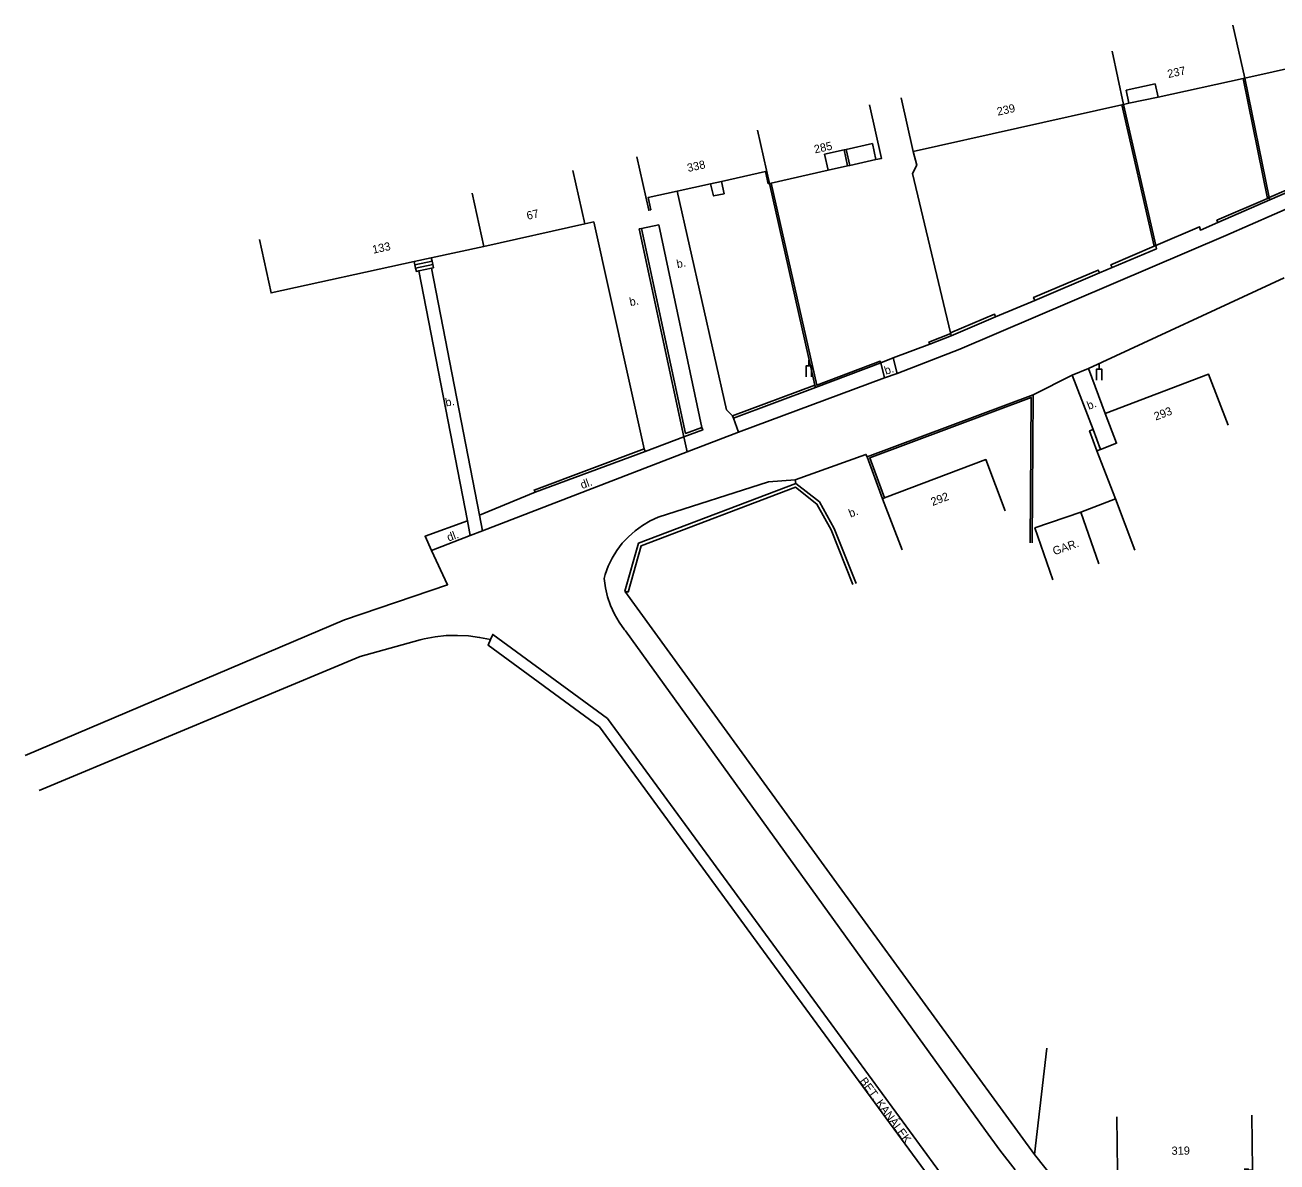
# Model space of a CAD drawing. Extents: x -582162 to -561283, y -1187583 to -1183539.
# Drawn here: x -575255.7 to -575141.2, y -1183913 to -1183809.1 of the extents above; entities that cross this region are included whole.
import ezdxf

# ---------------------------------------------------------------- set-up
doc = ezdxf.new("R2010")
doc.units = 0
for name, color, linetype in [('Vrstva 1', 7, 'Continuous'), ('Vrstva 10', 7, 'Continuous'), ('Vrstva 14', 7, 'Continuous'), ('Vrstva 4', 7, 'Continuous'), ('Vrstva 6', 7, 'Continuous'), ('Vrstva 9', 7, 'Continuous')]:
    doc.layers.add(name, color=color, linetype=linetype)

# ---------------------------------------------------------------- blocks, each defined once
blk = doc.blocks.new('4.120')
at = {"layer": 'Vrstva 1'}
blk.add_line((0, 2), (0, 3), dxfattribs=at)
blk.add_lwpolyline([(-0.5, 0), (-0.5, 2), (0.5, 2), (0.5, 0)], dxfattribs=at)

msp = doc.modelspace()

# ---------------------------------------------------------------- linework, layer by layer
at = {"layer": 'Vrstva 10'}
for points in [[(-575191.01, -1183844.78), (-575191.57, -1183844.23), (-575196.06, -1183824.24)], [(-575175.95, -1183840.92), (-575170.24, -1183838.68), (-575145.92, -1183828.3), (-575137, -1183824.39)], [(-575204.52, -1183827.23), (-575203.7, -1183827.05), (-575199.08, -1183847.81)], [(-575193.82, -1183845.85), (-575197.76, -1183827.33), (-575199.33, -1183827.64)], [(-575218.53, -1183831.28), (-575214.16, -1183853.85)], [(-575215.26, -1183854.39), (-575219.68, -1183831.52)], [(-575140.57, -1183832.16), (-575158.46, -1183840.46)], [(-575158.46, -1183840.46), (-575159.96, -1183841.06)], [(-575156.93, -1183844.57), (-575158.46, -1183840.46)], [(-575190.48, -1183846.26), (-575177.11, -1183841.3)], [(-575177.11, -1183841.3), (-575175.95, -1183840.92)], [(-575159.96, -1183841.06), (-575163.54, -1183842.86)], [(-575159.96, -1183841.06), (-575158.04, -1183846.03)], [(-575190.93, -1183844.99), (-575190.48, -1183846.26)], [(-575199, -1183848.03), (-575195.47, -1183846.69)], [(-575195.47, -1183846.69), (-575195.17, -1183848.06)], [(-575195.17, -1183848.06), (-575190.48, -1183846.26)], [(-575213.88, -1183855.28), (-575195.17, -1183848.06)], [(-575178.7, -1183848.54), (-575178.81, -1183848.31), (-575185.28, -1183850.64)], [(-575185.28, -1183850.64), (-575187.72, -1183850.81), (-575197.8, -1183854.03), (-575198.55, -1183854.38), (-575199.25, -1183854.8), (-575199.92, -1183855.28), (-575200.53, -1183855.83), (-575201.09, -1183856.43), (-575201.58, -1183857.09), (-575202.01, -1183857.79), (-575202.37, -1183858.53), (-575202.66, -1183859.3), (-575202.76, -1183859.65), (-575202.64, -1183860.49), (-575202.43, -1183861.32), (-575202.16, -1183862.13), (-575201.8, -1183862.9), (-575201.38, -1183863.64), (-575200.89, -1183864.34), (-575200.8, -1183864.45), (-575183.27, -1183888.75), (-575167.87, -1183910.11), (-575166.56, -1183911.93), (-575165.18, -1183913.7)], [(-575185.22, -1183850.97), (-575185.28, -1183850.64)], [(-575214.16, -1183853.85), (-575209.06, -1183851.77)], [(-575214.16, -1183853.85), (-575213.88, -1183855.28)], [(-575215.26, -1183854.39), (-575219.13, -1183855.79), (-575218.53, -1183857.08)], [(-575215.01, -1183855.72), (-575215.26, -1183854.39)], [(-575215.01, -1183855.72), (-575213.88, -1183855.28)], [(-575218.53, -1183857.08), (-575215.01, -1183855.72)], [(-575255.7, -1183875.83), (-575226.48, -1183863.42), (-575217.07, -1183860.22), (-575218.53, -1183857.08)], [(-575254.42, -1183879.04), (-575225.06, -1183866.77), (-575219.58, -1183865.26), (-575219.21, -1183865.17), (-575218.2, -1183864.98), (-575217.19, -1183864.87), (-575216.17, -1183864.85), (-575215.15, -1183864.9), (-575214.14, -1183865.03), (-575213.14, -1183865.24)], [(-575213.14, -1183865.24), (-575213.37, -1183865.75), (-575203.18, -1183873.21), (-575188.19, -1183893.71), (-575166.83, -1183922.84)], [(-575213.14, -1183865.24), (-575212.94, -1183864.77), (-575202.43, -1183872.46), (-575187.34, -1183893.09), (-575166.1, -1183922.09), (-575164.28, -1183923.82), (-575162.4, -1183925.5), (-575160.48, -1183927.11), (-575158.5, -1183928.67), (-575156.47, -1183930.16), (-575154.4, -1183931.58), (-575152.28, -1183932.94), (-575150.12, -1183934.23), (-575147.92, -1183935.44), (-575145.69, -1183936.59), (-575143.41, -1183937.67), (-575141.9, -1183938.34), (-575138.51, -1183939.45), (-575135.1, -1183940.49), (-575131.67, -1183941.45), (-575128.21, -1183942.33), (-575124.74, -1183943.13), (-575121.49, -1183943.8)]]:
    msp.add_lwpolyline(points, dxfattribs=at)
at = {"layer": 'Vrstva 4'}
for points in [[(-575145.26, -1183809.05), (-575144.17, -1183813.92)], [(-575126.86, -1183810.05), (-575144.17, -1183813.92)], [(-575156.31, -1183811.43), (-575155.26, -1183816.31)], [(-575144.32, -1183813.95), (-575152.1, -1183815.63)], [(-575144.17, -1183813.92), (-575144.32, -1183813.95)], [(-575155.03, -1183815.01), (-575154.77, -1183816.2)], [(-575152.36, -1183814.43), (-575152.1, -1183815.63)], [(-575178.48, -1183816.36), (-575177.39, -1183821.24), (-575177.9, -1183821.35)], [(-575174.51, -1183820.6), (-575175.6, -1183815.72)], [(-575155.41, -1183816.34), (-575174.51, -1183820.6)], [(-575155.26, -1183816.31), (-575155.41, -1183816.34)], [(-575154.77, -1183816.2), (-575155.26, -1183816.31)], [(-575152.1, -1183815.63), (-575154.77, -1183816.2)], [(-575188.72, -1183818.65), (-575187.63, -1183823.53)], [(-575178.22, -1183819.89), (-575177.9, -1183821.35)], [(-575180.82, -1183820.47), (-575182.6, -1183820.87), (-575182.28, -1183822.33)], [(-575180.63, -1183820.43), (-575180.82, -1183820.47)], [(-575180.82, -1183820.47), (-575180.5, -1183821.93)], [(-575180.3, -1183821.89), (-575180.63, -1183820.43)], [(-575199.76, -1183821.1), (-575198.68, -1183825.98), (-575198.49, -1183825.93), (-575198.73, -1183824.83), (-575196.06, -1183824.24)], [(-575180.5, -1183821.93), (-575182.28, -1183822.33)], [(-575180.3, -1183821.89), (-575180.5, -1183821.93)], [(-575177.9, -1183821.35), (-575180.3, -1183821.89)], [(-575205.61, -1183822.35), (-575204.52, -1183827.23)], [(-575193.03, -1183823.57), (-575192.03, -1183823.35)], [(-575192.03, -1183823.35), (-575187.99, -1183822.45), (-575187.75, -1183823.56), (-575187.63, -1183823.53)], [(-575182.28, -1183822.33), (-575187.48, -1183823.5)], [(-575214.83, -1183824.41), (-575213.74, -1183829.29)], [(-575196.06, -1183824.24), (-575193.03, -1183823.57)], [(-575187.48, -1183823.5), (-575187.63, -1183823.53)], [(-575204.52, -1183827.23), (-575213.74, -1183829.29)], [(-575220.11, -1183830.68), (-575233.2, -1183833.54), (-575234.27, -1183828.65)], [(-575213.74, -1183829.29), (-575218.56, -1183830.34)], [(-575218.56, -1183830.34), (-575220.11, -1183830.68)], [(-575145.7, -1183845.64), (-575147.48, -1183840.97), (-575156.93, -1183844.57)], [(-575156.93, -1183844.57), (-575155.9, -1183847.28), (-575157.37, -1183847.85)], [(-575157.37, -1183847.85), (-575157.69, -1183847.97)], [(-575157.69, -1183847.97), (-575156.01, -1183852.38)], [(-575177.11, -1183852.29), (-575167.85, -1183848.78), (-575166.08, -1183853.45)], [(-575177.29, -1183852.36), (-575177.11, -1183852.29)], [(-575175.51, -1183857.04), (-575177.29, -1183852.36)], [(-575156.01, -1183852.38), (-575154.24, -1183857.05)], [(-575161.72, -1183859.76), (-575163.36, -1183855.03), (-575159.16, -1183853.58)], [(-575159.16, -1183853.58), (-575157.52, -1183858.31)], [(-575155.87, -1183908.88), (-575155.83, -1183913.88)], [(-575144.22, -1183913.64), (-575143.86, -1183913.64), (-575143.86, -1183913.74), (-575143.48, -1183913.72), (-575143.52, -1183908.72)]]:
    msp.add_lwpolyline(points, dxfattribs=at)
at = {"layer": 'Vrstva 9'}
for points in [[(-575144.32, -1183813.95), (-575142.1, -1183824.9)], [(-575144.17, -1183813.92), (-575141.94, -1183824.83)], [(-575155.03, -1183815.01), (-575152.36, -1183814.43)], [(-575155.41, -1183816.34), (-575152.47, -1183829.28)], [(-575155.26, -1183816.31), (-575152.32, -1183829.22)], [(-575180.63, -1183820.43), (-575178.22, -1183819.89)], [(-575171.08, -1183837.18), (-575174.56, -1183822.62), (-575174.17, -1183821.86), (-575174.51, -1183820.6)], [(-575193.03, -1183823.57), (-575192.75, -1183824.68), (-575191.78, -1183824.48), (-575192.03, -1183823.35)], [(-575141.94, -1183824.83), (-575137.29, -1183822.82), (-575137.21, -1183823)], [(-575141.9, -1183825.03), (-575137.53, -1183823.14)], [(-575183.48, -1183841.96), (-575187.63, -1183823.53)], [(-575187.48, -1183823.5), (-575183.32, -1183841.99), (-575177.52, -1183839.78), (-575177.46, -1183839.92)], [(-575146.65, -1183827.1), (-575146.73, -1183826.9), (-575142.1, -1183824.9)], [(-575141.9, -1183825.03), (-575146.65, -1183827.1)], [(-575142.1, -1183824.9), (-575141.94, -1183824.83)], [(-575141.94, -1183824.83), (-575141.9, -1183825.03)], [(-575199.33, -1183827.64), (-575199.55, -1183827.69)], [(-575199.55, -1183827.69), (-575195.47, -1183846.69)], [(-575193.82, -1183845.85), (-575195.3, -1183846.38), (-575199.33, -1183827.64)], [(-575146.65, -1183827.1), (-575148.24, -1183827.79), (-575148.33, -1183827.49), (-575152.32, -1183829.22)], [(-575152.47, -1183829.28), (-575156.42, -1183830.96), (-575156.31, -1183831.22)], [(-575152.32, -1183829.22), (-575152.26, -1183829.5), (-575156.31, -1183831.22)], [(-575152.32, -1183829.22), (-575152.47, -1183829.28)], [(-575220.11, -1183830.68), (-575220.05, -1183830.98)], [(-575218.49, -1183830.64), (-575220.05, -1183830.98)], [(-575220.05, -1183830.98), (-575219.99, -1183831.27)], [(-575218.43, -1183830.93), (-575219.99, -1183831.27)], [(-575219.99, -1183831.27), (-575219.92, -1183831.57), (-575219.68, -1183831.52)], [(-575219.68, -1183831.52), (-575218.53, -1183831.28)], [(-575218.49, -1183830.64), (-575218.56, -1183830.34)], [(-575218.53, -1183831.28), (-575218.36, -1183831.24), (-575218.43, -1183830.93)], [(-575218.43, -1183830.93), (-575218.49, -1183830.64)], [(-575157.47, -1183831.71), (-575156.31, -1183831.22)], [(-575163.38, -1183834.22), (-575163.49, -1183833.96), (-575157.57, -1183831.45), (-575157.47, -1183831.71)], [(-575157.47, -1183831.71), (-575163.38, -1183834.22)], [(-575166.96, -1183835.74), (-575163.38, -1183834.22)], [(-575171.08, -1183837.18), (-575167.07, -1183835.48), (-575166.96, -1183835.74)], [(-575171.01, -1183837.46), (-575166.96, -1183835.74)], [(-575176.33, -1183839.48), (-575172.97, -1183838.22)], [(-575172.97, -1183838.22), (-575173.05, -1183838.03), (-575171.06, -1183837.26)], [(-575172.97, -1183838.22), (-575171.01, -1183837.46)], [(-575171.06, -1183837.26), (-575171.08, -1183837.18)], [(-575171.01, -1183837.46), (-575171.06, -1183837.26)], [(-575177.46, -1183839.92), (-575183.43, -1183842.19)], [(-575177.46, -1183839.92), (-575176.33, -1183839.48)], [(-575177.46, -1183839.92), (-575177.11, -1183841.3)], [(-575175.95, -1183840.92), (-575176.33, -1183839.48)], [(-575191.01, -1183844.78), (-575183.48, -1183841.96)], [(-575183.43, -1183842.19), (-575190.93, -1183844.99)], [(-575183.43, -1183842.19), (-575183.48, -1183841.96)], [(-575163.54, -1183842.86), (-575178.7, -1183848.54)], [(-575163.79, -1183856.4), (-575163.7, -1183843.09), (-575178.47, -1183848.62), (-575177.11, -1183852.29)], [(-575163.63, -1183856.4), (-575163.54, -1183842.86)], [(-575190.93, -1183844.99), (-575191.01, -1183844.78)], [(-575195.47, -1183846.69), (-575193.74, -1183846.07), (-575193.82, -1183845.85)], [(-575158.04, -1183846.03), (-575158.37, -1183846.16), (-575157.69, -1183847.97)], [(-575158.04, -1183846.03), (-575157.37, -1183847.85)], [(-575209.06, -1183851.77), (-575209.15, -1183851.56), (-575199.08, -1183847.81)], [(-575199, -1183848.03), (-575209.06, -1183851.77)], [(-575199.08, -1183847.81), (-575199, -1183848.03)], [(-575178.7, -1183848.54), (-575177.29, -1183852.36)], [(-575200.86, -1183860.81), (-575199.62, -1183856.43), (-575185.22, -1183850.97)], [(-575200.86, -1183860.81), (-575200.57, -1183860.89), (-575199.37, -1183856.65), (-575185.27, -1183851.31), (-575183.3, -1183852.84), (-575181.98, -1183855.21), (-575180, -1183860.21)], [(-575185.22, -1183850.97), (-575183.07, -1183852.64), (-575181.71, -1183855.08), (-575179.72, -1183860.1)], [(-575156.01, -1183852.38), (-575159.16, -1183853.58)], [(-575163.41, -1183912.31), (-575181.26, -1183887.81), (-575200.86, -1183860.81)], [(-575162.28, -1183902.58), (-575163.41, -1183912.31)], [(-575159.76, -1183916.91), (-575163.41, -1183912.31)]]:
    msp.add_lwpolyline(points, dxfattribs=at)

# ---------------------------------------------------------------- block references
at = {"layer": 'Vrstva 9', "xscale": 0.5, "yscale": 0.5}
for p in [(-575184.03, -1183841.2), (-575157.49, -1183841.52)]:
    msp.add_blockref('4.120', p, dxfattribs=at)

# ---------------------------------------------------------------- texts
at = {"layer": 'Vrstva 14'}
for s, rotation, p in [('b.', 11.373, (-575196.05, -1183831.28)), ('b.', 11.373, (-575200.36, -1183834.75)), ('b.', 18.316, (-575176.99, -1183841.03)), ('b.', 11.016, (-575217.2, -1183843.94)), ('b.', 20.845, (-575158.44, -1183844.23)), ('dl.', 20.414, (-575204.76, -1183851.48)), ('b.', 20.845, (-575180.23, -1183854.08)), ('dl.', 19.931, (-575216.97, -1183856.28)), ('GAR.', 19.108, (-575161.59, -1183857.53)), ('BET. KANÁLEK', 306.246, (-575179.43, -1183905.6))]:
    msp.add_text(s, height=0.75, rotation=rotation, dxfattribs=at).set_placement(p)
at = {"layer": 'Vrstva 6'}
for s, rotation, p in [('237', 12.15, (-575151.16, -1183813.9)), ('239', 12.566, (-575166.75, -1183817.34)), ('285', 12.595, (-575183.47, -1183820.79)), ('338', 12.485, (-575195.07, -1183822.49)), ('67', 12.615, (-575209.75, -1183826.86)), ('133', 12.312, (-575223.86, -1183829.96)), ('293', 20.846, (-575152.31, -1183845.22)), ('292', 20.809, (-575172.72, -1183853.03)), ('319', 0.436, (-575150.87, -1183912.34))]:
    msp.add_text(s, height=0.75, rotation=rotation, dxfattribs=at).set_placement(p)

doc.saveas('drawing.dxf')
